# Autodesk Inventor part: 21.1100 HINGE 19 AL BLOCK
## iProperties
Created: 2007-01
Part Number: 21.1100 HINGE 19 AL BLOCK
Document SubType Name: Modeling
Designer: Andy Moles
Material: Aluminum-6061
Density: 2.71 g/cm^3
Mass: 23.3972 g
Surface Area: 49.8304 cm^2
Volume: 8.63367 cm^3
Author: Andy Moles
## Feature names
1. Extrusion1
2. Hole1
3. Hole2
